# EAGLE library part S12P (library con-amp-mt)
AMP MT CONNECTOR
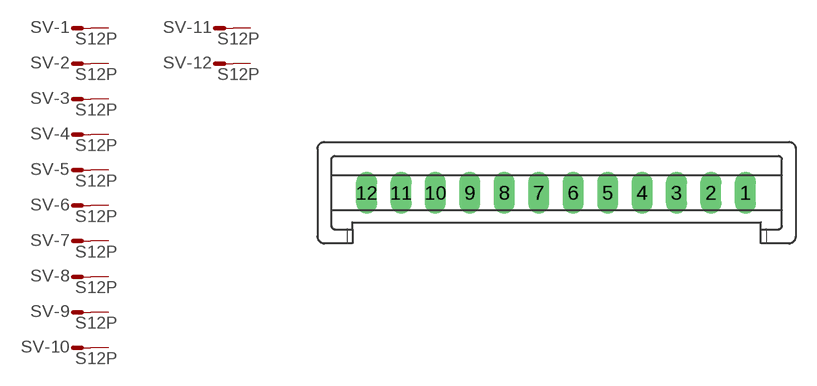
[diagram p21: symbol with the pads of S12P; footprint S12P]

Designator prefix SV; gates -1=M -2=M -3=M -4=M -5=M -6=M -7=M -8=M -9=M -10=M -11=M -12=M

## S12P (OC_FARNELL: unknown; OC_NEWARK: unknown)  [S12P]
1  -1:S  pas
2  -2:S  pas
3  -3:S  pas
4  -4:S  pas
5  -5:S  pas
6  -6:S  pas
7  -7:S  pas
8  -8:S  pas
9  -9:S  pas
10  -10:S  pas
11  -11:S  pas
12  -12:S  pas

## Footprint S12P (pad centres in mm)
AMP MT CONNECTOR
drill 1.016 long: 1 13.75,0; 2 11.25,0; 3 8.75,0; 4 6.25,0; 5 3.75,0; 6 1.25,0; 7 -1.25,0; 8 -3.75,0; 9 -6.25,0; 10 -8.75,0; 11 -11.25,0; 12 -13.75,0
